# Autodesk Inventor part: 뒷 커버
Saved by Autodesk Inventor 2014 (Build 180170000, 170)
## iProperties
Created: 2026-06
Part Number: 뒷 커버
Material: 알루미늄 6061
Document SubType Name: Modeling
Designer: dg
Density: 2.71 g/cm^3
Appearance: 알루미늄 - 평지
Mass: 44.3564 g
Surface Area: 68.2721 cm^2
Volume: 16.3677 cm^3
Author: jhkim
Creation Date: 2026-05-29
Sending System: Autodesk Inventor 2027
Preprocessor: ST-DEVELOPER v20.1
Author: dg
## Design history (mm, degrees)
node "뒷 커버1"
node "솔리드1"
node "기준1"
